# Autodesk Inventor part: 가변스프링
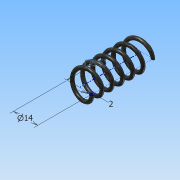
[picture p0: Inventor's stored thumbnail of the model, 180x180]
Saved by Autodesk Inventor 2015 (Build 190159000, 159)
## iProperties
Created: 2020-02
Part Number: 가변스프링
Material: 강철
Document SubType Name: Modeling
Designer: user
Density: 7.85 g/cm^3
Appearance: 플레이트
Mass: 6.42998 g
Surface Area: 16.6202 cm^2
Volume: 0.819106 cm^3
Author: user
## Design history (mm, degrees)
sketch "스케치1"
  geometry: L1 (0, 0)-(7, 0); L2 (7, 0)-(7, 35.5); L3 (7, 35.5)-(0, 35.5); L4 (0, 35.5)-(0, 0); C1 r 1 at (7, 0)
  constraints: 8 end point, 2 parallel, 1 centre point, 1 coincident, 1 horizontal, 1 perpendicular
  dimensions: "d0" = 35.5 distance of L3.end L1.start (derived); "d1" = 2 diameter of C1; "d2" = 14 diameter of L2 L4
feature "코일1" sketch "스케치1" pitch "d3" = 10; turns "d5" = 6; dims "d4" = 35.5 (= d0), "d6" = 0, angle "d7" = 90 deg, angle "d8" = 90 deg, "d9" = 0, "d10" = 0
sketch "스케치2"
  geometry: C1 r 16.111 at (0, 0); 1 further point
  constraints: 1 centre point, 1 coincident
extrude "돌출1" cut sketch "스케치2" distance "d11" = 10; taper "d12" = 0 deg
node "작업 평면1"
sketch "스케치3"
  geometry: C1 r 16.525 at (7, 0); 1 further point
  constraints: 1 centre point, 1 coincident
extrude "돌출2" cut sketch "스케치3" distance "d14" = 10; taper "d15" = 0 deg
node "솔리드1"
other parameters: "d13" = 90 deg
